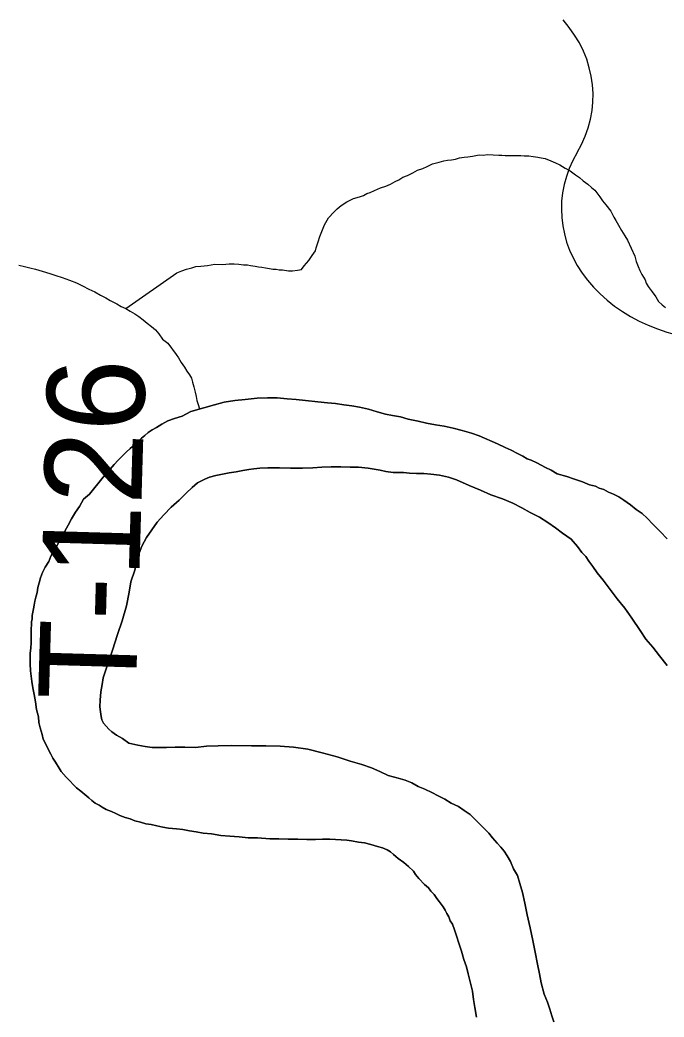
# Model space of a CAD drawing. Extents: x 2.4 to 73.1, y 4.5 to 25.6.
# Drawn here: x 30.7828 to 30.9703, y 21.8149 to 22.105 of the extents above; entities that cross this region are included whole.
import ezdxf

# ---------------------------------------------------------------- set-up
doc = ezdxf.new("R2010")
doc.units = 0
for name, color, linetype in [('GM_X_Major_River', 7, 'Continuous'), ('GM_X_Minor_River', 7, 'Continuous'), ('GM_X_Township_Road_Text', 7, 'Continuous'), ('GM_X_US_Shield', 7, 'Continuous')]:
    doc.layers.add(name, color=color, linetype=linetype)

msp = doc.modelspace()

# ---------------------------------------------------------------- linework, layer by layer
at = {"layer": 'GM_X_Major_River'}
for points in [[(30.92574, 21.97985), (30.92404, 21.98063), (30.92177, 21.98162), (30.91648, 21.98399), (30.91421, 21.98478), (30.91156, 21.98559), (30.90891, 21.9862), (30.90626, 21.98681), (30.90379, 21.98723), (30.90114, 21.98766), (30.89867, 21.98827), (30.89583, 21.98888), (30.89356, 21.98949), (30.89128, 21.98991), (30.8892, 21.99032), (30.88673, 21.99093), (30.88427, 21.99173), (30.88162, 21.99234), (30.87935, 21.99276), (30.87707, 21.99299), (30.8746, 21.99341), (30.87232, 21.99363), (30.86947, 21.99387), (30.86587, 21.99431), (30.86321, 21.99454), (30.86055, 21.99478), (30.8577, 21.99501), (30.85485, 21.99506), (30.8518, 21.99492), (30.84837, 21.99459), (30.84533, 21.99426), (30.84228, 21.99374), (30.83941, 21.99303), (30.83635, 21.99213), (30.83253, 21.99105), (30.83004, 21.98976), (30.82775, 21.98904), (30.82583, 21.98831), (30.82411, 21.98739), (30.82257, 21.98646), (30.82123, 21.98572), (30.82008, 21.98498), (30.81911, 21.98405), (30.81815, 21.98331), (30.81718, 21.98237), (30.81622, 21.98144), (30.81487, 21.98032), (30.81371, 21.9792), (30.81255, 21.97807), (30.81139, 21.97695), (30.81023, 21.97564), (30.80907, 21.97433), (30.80791, 21.97302), (30.80422, 21.96852), (30.80306, 21.96702), (30.80132, 21.96553), (30.80015, 21.96346), (30.79898, 21.96177), (30.79781, 21.95988), (30.79683, 21.958), (30.79585, 21.95631), (30.79507, 21.9548), (30.79429, 21.95348), (30.7935, 21.95197), (30.79253, 21.95047), (30.79175, 21.94896), (30.79115, 21.94745), (30.79017, 21.94576), (30.78939, 21.94425), (30.7888, 21.94274), (30.78839, 21.94123), (30.78799, 21.9399), (30.78778, 21.93839), (30.78737, 21.93706), (30.78717, 21.93593), (30.78696, 21.93479), (30.78675, 21.93365), (30.78655, 21.93271), (30.78634, 21.93176), (30.78633, 21.93081), (30.78612, 21.92986), (30.78611, 21.92891), (30.78609, 21.92796), (30.78607, 21.92682), (30.78605, 21.9253), (30.78603, 21.92379), (30.786, 21.92227), (30.78579, 21.92075), (30.78576, 21.91923), (30.78574, 21.91771), (30.7859, 21.91562), (30.78606, 21.91409), (30.78623, 21.91257), (30.78658, 21.91067), (30.78693, 21.90876), (30.78728, 21.90666), (30.78762, 21.90438), (30.78816, 21.90228), (30.78832, 21.90057), (30.78868, 21.89904), (30.78922, 21.89713)], [(30.78922, 21.89713), (30.78868, 21.89904), (30.78832, 21.90057), (30.78816, 21.90228), (30.78762, 21.90438), (30.78728, 21.90666), (30.78693, 21.90876), (30.78658, 21.91067), (30.78623, 21.91257), (30.78606, 21.91409), (30.7859, 21.91562), (30.78574, 21.91771), (30.78576, 21.91923), (30.78579, 21.92075), (30.786, 21.92227), (30.78603, 21.92379), (30.78605, 21.9253), (30.78607, 21.92682), (30.78609, 21.92796), (30.78611, 21.92891), (30.78612, 21.92986), (30.78633, 21.93081), (30.78634, 21.93176), (30.78655, 21.93271), (30.78675, 21.93365), (30.78696, 21.93479), (30.78717, 21.93593), (30.78737, 21.93706), (30.78778, 21.93839), (30.78799, 21.9399), (30.78839, 21.94123), (30.7888, 21.94274), (30.78939, 21.94425), (30.79017, 21.94576), (30.79115, 21.94745), (30.79175, 21.94896), (30.79253, 21.95047), (30.7935, 21.95197), (30.79429, 21.95348), (30.79507, 21.9548), (30.79585, 21.95631), (30.79683, 21.958), (30.79781, 21.95988), (30.79898, 21.96177), (30.80015, 21.96346), (30.80132, 21.96553), (30.80306, 21.96702), (30.80422, 21.96852), (30.80791, 21.97302), (30.80907, 21.97433), (30.81023, 21.97564), (30.81139, 21.97695), (30.81255, 21.97807), (30.81371, 21.9792), (30.81487, 21.98032), (30.81622, 21.98144), (30.81718, 21.98237), (30.81815, 21.98331), (30.81911, 21.98405), (30.82008, 21.98498), (30.82123, 21.98572), (30.82257, 21.98646), (30.82411, 21.98739), (30.82583, 21.98831), (30.82775, 21.98904), (30.83004, 21.98976), (30.83253, 21.99105), (30.83635, 21.99213), (30.83941, 21.99303), (30.84228, 21.99374), (30.84533, 21.99426), (30.84837, 21.99459), (30.8518, 21.99492), (30.85485, 21.99506), (30.8577, 21.99501), (30.86055, 21.99478), (30.86321, 21.99454), (30.86587, 21.99431), (30.86947, 21.99387), (30.87232, 21.99363), (30.8746, 21.99341), (30.87707, 21.99299), (30.87935, 21.99276), (30.88162, 21.99234), (30.88427, 21.99173), (30.88673, 21.99093), (30.8892, 21.99032), (30.89128, 21.98991), (30.89356, 21.98949), (30.89583, 21.98888), (30.89867, 21.98827), (30.90114, 21.98766), (30.90379, 21.98723), (30.90626, 21.98681), (30.90891, 21.9862), (30.91156, 21.98559), (30.91421, 21.98478), (30.91648, 21.98399), (30.92177, 21.98162), (30.92404, 21.98063), (30.92574, 21.97985)], [(30.97117, 21.95403), (30.96911, 21.95615), (30.96705, 21.95828), (30.96537, 21.96001), (30.96387, 21.96137), (30.96217, 21.96254), (30.96048, 21.96389), (30.9586, 21.96525), (30.95709, 21.96623), (30.95558, 21.96701), (30.95407, 21.96761), (30.95275, 21.96839), (30.95143, 21.96879), (30.9503, 21.96938), (30.94859, 21.96979), (30.94651, 21.97058), (30.94424, 21.97138), (30.94197, 21.97217), (30.93913, 21.97298), (30.93744, 21.97396), (30.93574, 21.97474), (30.93329, 21.97611), (30.93159, 21.9769), (30.93045, 21.9773), (30.92913, 21.97808), (30.92762, 21.97887), (30.92574, 21.97985)], [(30.92574, 21.97985), (30.92762, 21.97887), (30.92913, 21.97808), (30.93045, 21.9773), (30.93159, 21.9769), (30.93329, 21.97611), (30.93574, 21.97474), (30.93744, 21.97396), (30.93913, 21.97298), (30.94197, 21.97217), (30.94424, 21.97138), (30.94651, 21.97058), (30.94859, 21.96979), (30.9503, 21.96938), (30.95143, 21.96879), (30.95275, 21.96839), (30.95407, 21.96761), (30.95558, 21.96701), (30.95709, 21.96623), (30.9586, 21.96525), (30.96048, 21.96389), (30.96217, 21.96254), (30.96387, 21.96137), (30.96537, 21.96001), (30.96705, 21.95828), (30.96911, 21.95615), (30.97117, 21.95403)], [(30.93206, 21.83724), (30.93135, 21.84086), (30.93046, 21.84467), (30.92976, 21.8481), (30.92904, 21.85116), (30.92832, 21.85383), (30.9276, 21.85612), (30.92649, 21.85804), (30.92557, 21.86014), (30.92465, 21.86187), (30.92372, 21.86321), (30.92278, 21.86437), (30.92166, 21.86553), (30.92035, 21.86707), (30.91923, 21.86842), (30.91792, 21.86977), (30.9138, 21.87382), (30.91211, 21.87499), (30.91042, 21.87616), (30.90834, 21.87714), (30.90646, 21.87831), (30.90457, 21.87929), (30.90269, 21.88028), (30.90061, 21.88126), (30.89872, 21.88205), (30.89683, 21.88303), (30.89494, 21.88382), (30.89286, 21.88443), (30.89002, 21.88523), (30.88757, 21.88641), (30.88511, 21.8874), (30.88227, 21.8884), (30.87887, 21.8894), (30.87508, 21.8906), (30.87073, 21.89181), (30.86656, 21.89283), (30.86238, 21.89347), (30.85858, 21.89372), (30.8544, 21.89379), (30.85022, 21.89386), (30.84451, 21.89395), (30.84052, 21.89383), (30.83709, 21.89369), (30.83385, 21.89336), (30.83081, 21.89341), (30.82796, 21.89346), (30.82549, 21.89331), (30.82339, 21.89335), (30.8213, 21.89338), (30.81921, 21.8936), (30.81713, 21.89402), (30.81448, 21.89463), (30.8126, 21.89599), (30.8109, 21.89697), (30.80958, 21.89794), (30.80864, 21.89872), (30.80715, 21.90045), (30.80659, 21.90141), (30.80642, 21.90236), (30.80625, 21.9037), (30.80608, 21.90522), (30.80611, 21.90712), (30.80634, 21.90958), (30.80676, 21.91167), (30.80698, 21.91356), (30.80976, 21.92169), (30.81117, 21.92623), (30.81256, 21.93019), (30.81377, 21.93454), (30.81459, 21.93852), (30.81502, 21.94155), (30.81622, 21.94495), (30.81723, 21.94912), (30.81823, 21.95195), (30.8196, 21.9544), (30.82115, 21.95665), (30.82271, 21.95891), (30.82464, 21.96097), (30.82677, 21.96321), (30.82909, 21.96527), (30.83121, 21.96732), (30.83295, 21.969), (30.83449, 21.97031), (30.8366, 21.97141), (30.83794, 21.97196), (30.83985, 21.9725), (30.84176, 21.97285), (30.84367, 21.9732), (30.84576, 21.97354), (30.84767, 21.97389), (30.84939, 21.97425), (30.85091, 21.97441), (30.85263, 21.97457), (30.85491, 21.97473), (30.85833, 21.97467), (30.86156, 21.97462), (30.86499, 21.97456), (30.86803, 21.9747), (30.8707, 21.97485), (30.87336, 21.975), (30.87621, 21.97495)], [(30.87621, 21.97495), (30.87336, 21.975), (30.8707, 21.97485), (30.86803, 21.9747), (30.86499, 21.97456), (30.86156, 21.97462), (30.85833, 21.97467), (30.85491, 21.97473), (30.85263, 21.97457), (30.85091, 21.97441), (30.84939, 21.97425), (30.84767, 21.97389), (30.84576, 21.97354), (30.84367, 21.9732), (30.84176, 21.97285), (30.83985, 21.9725), (30.83794, 21.97196), (30.8366, 21.97141), (30.83449, 21.97031), (30.83295, 21.969), (30.83121, 21.96732), (30.82909, 21.96527), (30.82677, 21.96321), (30.82464, 21.96097), (30.82271, 21.95891), (30.82115, 21.95665), (30.8196, 21.9544), (30.81823, 21.95195), (30.81723, 21.94912), (30.81622, 21.94495), (30.81502, 21.94155), (30.81459, 21.93852), (30.81377, 21.93454), (30.81256, 21.93019), (30.81117, 21.92623), (30.80976, 21.92169), (30.80698, 21.91356), (30.80676, 21.91167), (30.80634, 21.90958), (30.80611, 21.90712), (30.80608, 21.90522), (30.80625, 21.9037), (30.80642, 21.90236), (30.80659, 21.90141), (30.80715, 21.90045), (30.80864, 21.89872), (30.80958, 21.89794), (30.8109, 21.89697), (30.8126, 21.89599), (30.81448, 21.89463), (30.81713, 21.89402), (30.81921, 21.8936), (30.8213, 21.89338), (30.82339, 21.89335), (30.82549, 21.89331), (30.82796, 21.89346), (30.83081, 21.89341), (30.83385, 21.89336), (30.83709, 21.89369), (30.84052, 21.89383), (30.84451, 21.89395), (30.85022, 21.89386), (30.8544, 21.89379), (30.85858, 21.89372), (30.86238, 21.89347), (30.86656, 21.89283), (30.87073, 21.89181), (30.87508, 21.8906), (30.87887, 21.8894), (30.88227, 21.8884), (30.88511, 21.8874), (30.88757, 21.88641), (30.89002, 21.88523), (30.89286, 21.88443), (30.89494, 21.88382), (30.89683, 21.88303), (30.89872, 21.88205), (30.90061, 21.88126), (30.90269, 21.88028), (30.90457, 21.87929), (30.90646, 21.87831), (30.90834, 21.87714), (30.91042, 21.87616), (30.91211, 21.87499), (30.9138, 21.87382), (30.91792, 21.86977), (30.91923, 21.86842), (30.92035, 21.86707), (30.92166, 21.86553), (30.92278, 21.86437), (30.92372, 21.86321), (30.92465, 21.86187), (30.92557, 21.86014), (30.92649, 21.85804), (30.9276, 21.85612), (30.92832, 21.85383), (30.92904, 21.85116), (30.92976, 21.8481), (30.93046, 21.84467), (30.93135, 21.84086), (30.93206, 21.83724)], [(30.87621, 21.97495), (30.87888, 21.97491), (30.88135, 21.97487), (30.8842, 21.97463), (30.88761, 21.974), (30.88932, 21.9736), (30.8914, 21.97337), (30.89235, 21.97336), (30.8933, 21.97334), (30.89445, 21.97332), (30.89615, 21.97311), (30.89825, 21.97307), (30.90034, 21.97304), (30.90242, 21.97281), (30.90489, 21.97258), (30.90755, 21.97197), (30.90982, 21.97117), (30.9136, 21.96959), (30.91681, 21.96821), (30.91983, 21.96683), (30.92323, 21.96564), (30.92626, 21.96445), (30.9289, 21.96307), (30.93135, 21.9617), (30.93399, 21.96033), (30.93644, 21.95877), (30.9387, 21.95722), (30.94076, 21.95566), (30.94321, 21.95391), (30.94508, 21.95179), (30.94638, 21.95006), (30.9475, 21.9489), (30.94843, 21.94756), (30.94955, 21.94602), (30.95085, 21.9441), (30.95253, 21.94198), (30.95458, 21.93929), (30.95663, 21.93659), (30.95887, 21.9339), (30.96092, 21.93101), (30.96333, 21.92736), (30.965, 21.92487), (30.96706, 21.92255), (30.96892, 21.92005), (30.97116, 21.91717)], [(30.97116, 21.91717), (30.96892, 21.92005), (30.96706, 21.92255), (30.965, 21.92487), (30.96333, 21.92736), (30.96092, 21.93101), (30.95887, 21.9339), (30.95663, 21.93659), (30.95458, 21.93929), (30.95253, 21.94198), (30.95085, 21.9441), (30.94955, 21.94602), (30.94843, 21.94756), (30.9475, 21.9489), (30.94638, 21.95006), (30.94508, 21.95179), (30.94321, 21.95391), (30.94076, 21.95566), (30.9387, 21.95722), (30.93644, 21.95877), (30.93399, 21.96033), (30.93135, 21.9617), (30.9289, 21.96307), (30.92626, 21.96445), (30.92323, 21.96564), (30.91983, 21.96683), (30.91681, 21.96821), (30.9136, 21.96959), (30.90982, 21.97117), (30.90755, 21.97197), (30.90489, 21.97258), (30.90242, 21.97281), (30.90034, 21.97304), (30.89825, 21.97307), (30.89615, 21.97311), (30.89445, 21.97332), (30.8933, 21.97334), (30.89235, 21.97336), (30.8914, 21.97337), (30.88932, 21.9736), (30.88761, 21.974), (30.8842, 21.97463), (30.88135, 21.97487), (30.87888, 21.97491), (30.87621, 21.97495)], [(30.78922, 21.89713), (30.78958, 21.8958), (30.79179, 21.89139), (30.79235, 21.89024), (30.79309, 21.88909), (30.7942, 21.88736), (30.79476, 21.8864), (30.79625, 21.88467), (30.79737, 21.88351), (30.79831, 21.88254), (30.79925, 21.88158), (30.80056, 21.88061), (30.80169, 21.87964), (30.80281, 21.87867), (30.80375, 21.87789), (30.80469, 21.87712), (30.80582, 21.87653), (30.80677, 21.87595), (30.8079, 21.87536), (30.80941, 21.87476), (30.81073, 21.87417), (30.81186, 21.87358), (30.81338, 21.87299), (30.81489, 21.87258), (30.81621, 21.87199), (30.81792, 21.87158), (30.81943, 21.87118), (30.82095, 21.87096), (30.82266, 21.87056), (30.82436, 21.87015), (30.82607, 21.86993), (30.82835, 21.8697), (30.83025, 21.86948), (30.83214, 21.86907), (30.83404, 21.86885), (30.83613, 21.86844), (30.83859, 21.86821), (30.84125, 21.86778), (30.84391, 21.86755), (30.84657, 21.86732), (30.84923, 21.86708), (30.85189, 21.86704), (30.8555, 21.86679), (30.85816, 21.86675), (30.86082, 21.86671), (30.86367, 21.86666), (30.86634, 21.86661), (30.86881, 21.86657), (30.8709, 21.86673), (30.87299, 21.8667), (30.87793, 21.86643), (30.87926, 21.86622), (30.88135, 21.8658), (30.88306, 21.86558), (30.88495, 21.86517), (30.88684, 21.86457), (30.88836, 21.86417), (30.88968, 21.86358), (30.89062, 21.86299), (30.89156, 21.86222), (30.89287, 21.86105), (30.89457, 21.85989), (30.89588, 21.85872), (30.89738, 21.85737), (30.89794, 21.85641), (30.89887, 21.85526), (30.90055, 21.85352), (30.90168, 21.85255), (30.90242, 21.85159), (30.90336, 21.85062), (30.9041, 21.84947), (30.90485, 21.84851), (30.90597, 21.84697), (30.90652, 21.84601), (30.90708, 21.84505), (30.90763, 21.84409), (30.908, 21.84295), (30.90874, 21.84199), (30.90928, 21.84027), (30.90983, 21.83855), (30.91055, 21.83645), (30.91128, 21.83415), (30.912, 21.83167), (30.91273, 21.82957), (30.91327, 21.82747), (30.9138, 21.82518), (30.91452, 21.82251), (30.91486, 21.82003), (30.91521, 21.81775), (30.91573, 21.81489)], [(30.91573, 21.81489), (30.91521, 21.81775), (30.91486, 21.82003), (30.91452, 21.82251), (30.9138, 21.82518), (30.91327, 21.82747), (30.91273, 21.82957), (30.912, 21.83167), (30.91128, 21.83415), (30.91055, 21.83645), (30.90983, 21.83855), (30.90928, 21.84027), (30.90874, 21.84199), (30.908, 21.84295), (30.90763, 21.84409), (30.90708, 21.84505), (30.90652, 21.84601), (30.90597, 21.84697), (30.90485, 21.84851), (30.9041, 21.84947), (30.90336, 21.85062), (30.90242, 21.85159), (30.90168, 21.85255), (30.90055, 21.85352), (30.89887, 21.85526), (30.89794, 21.85641), (30.89738, 21.85737), (30.89588, 21.85872), (30.89457, 21.85989), (30.89287, 21.86105), (30.89156, 21.86222), (30.89062, 21.86299), (30.88968, 21.86358), (30.88836, 21.86417), (30.88684, 21.86457), (30.88495, 21.86517), (30.88306, 21.86558), (30.88135, 21.8658), (30.87926, 21.86622), (30.87793, 21.86643), (30.87299, 21.8667), (30.8709, 21.86673), (30.86881, 21.86657), (30.86634, 21.86661), (30.86367, 21.86666), (30.86082, 21.86671), (30.85816, 21.86675), (30.8555, 21.86679), (30.85189, 21.86704), (30.84923, 21.86708), (30.84657, 21.86732), (30.84391, 21.86755), (30.84125, 21.86778), (30.83859, 21.86821), (30.83613, 21.86844), (30.83404, 21.86885), (30.83214, 21.86907), (30.83025, 21.86948), (30.82835, 21.8697), (30.82607, 21.86993), (30.82436, 21.87015), (30.82266, 21.87056), (30.82095, 21.87096), (30.81943, 21.87118), (30.81792, 21.87158), (30.81621, 21.87199), (30.81489, 21.87258), (30.81338, 21.87299), (30.81186, 21.87358), (30.81073, 21.87417), (30.80941, 21.87476), (30.8079, 21.87536), (30.80677, 21.87595), (30.80582, 21.87653), (30.80469, 21.87712), (30.80375, 21.87789), (30.80281, 21.87867), (30.80169, 21.87964), (30.80056, 21.88061), (30.79925, 21.88158), (30.79831, 21.88254), (30.79737, 21.88351), (30.79625, 21.88467), (30.79476, 21.8864), (30.7942, 21.88736), (30.79309, 21.88909), (30.79235, 21.89024), (30.79179, 21.89139), (30.78958, 21.8958), (30.78922, 21.89713)], [(30.93815, 21.81358), (30.93761, 21.8153), (30.93707, 21.8172), (30.93634, 21.81931), (30.93543, 21.8216), (30.93453, 21.82485), (30.934, 21.82751), (30.93347, 21.83037), (30.93276, 21.83381), (30.93206, 21.83724)], [(30.93206, 21.83724), (30.93276, 21.83381), (30.93347, 21.83037), (30.934, 21.82751), (30.93453, 21.82485), (30.93543, 21.8216), (30.93634, 21.81931), (30.93707, 21.8172), (30.93761, 21.8153), (30.93815, 21.81358)]]:
    msp.add_lwpolyline(points, dxfattribs=at)
at = {"layer": 'GM_X_Minor_River'}
for points in [[(30.81361, 22.021), (30.82841, 22.0314), (30.82994, 22.03194), (30.83128, 22.03249), (30.83281, 22.03285), (30.83396, 22.03321), (30.83548, 22.03337), (30.83738, 22.03353), (30.83948, 22.03388), (30.84176, 22.03384), (30.84367, 22.034), (30.84519, 22.03398), (30.84652, 22.03396), (30.84785, 22.03374), (30.84899, 22.03373), (30.84994, 22.03352), (30.85126, 22.03331), (30.85221, 22.0331), (30.85316, 22.03309), (30.8543, 22.03288), (30.85544, 22.03267), (30.85639, 22.03247), (30.85734, 22.03245), (30.85828, 22.03224), (30.85924, 22.03223), (30.86094, 22.03201), (30.86208, 22.03199), (30.86361, 22.03216), (30.86475, 22.03233), (30.86553, 22.03346), (30.86689, 22.03495), (30.86786, 22.03646), (30.86883, 22.03777), (30.86904, 22.03872), (30.86963, 22.04042), (30.87004, 22.04193), (30.87063, 22.04344), (30.87103, 22.04439), (30.87142, 22.04533), (30.8726, 22.0474), (30.87414, 22.04909), (30.87511, 22.05002), (30.87626, 22.05095), (30.87799, 22.05206), (30.87991, 22.05298), (30.88163, 22.05353), (30.88278, 22.05389), (30.88374, 22.05444), (30.88469, 22.05481), (30.88603, 22.05535), (30.88776, 22.05609), (30.88929, 22.05663), (30.89063, 22.05718), (30.89197, 22.05792), (30.89312, 22.05847), (30.89427, 22.05921), (30.89561, 22.05976), (30.89715, 22.06049), (30.89849, 22.06123), (30.90002, 22.06178), (30.90136, 22.06233), (30.90289, 22.06306), (30.9048, 22.0636), (30.90614, 22.06396), (30.90728, 22.06413), (30.90842, 22.0643), (30.90957, 22.06447), (30.91072, 22.06483), (30.91205, 22.065), (30.91319, 22.06517), (30.91453, 22.06534), (30.91548, 22.06552), (30.91644, 22.06569), (30.91758, 22.06567), (30.91891, 22.06584), (30.92214, 22.0656), (30.92309, 22.06558), (30.92404, 22.06557), (30.92518, 22.06555), (30.92613, 22.06553), (30.92708, 22.06552), (30.9286, 22.06549), (30.92955, 22.06548), (30.93088, 22.06546), (30.93221, 22.06525), (30.93354, 22.06503), (30.93449, 22.06483), (30.93563, 22.06462), (30.93733, 22.06402), (30.93865, 22.06343), (30.93997, 22.06284), (30.94148, 22.06187), (30.94299, 22.06108), (30.94449, 22.05992), (30.94562, 22.05914), (30.94675, 22.05817), (30.94806, 22.0572)], [(30.94806, 22.0572), (30.94919, 22.05623), (30.95013, 22.05545), (30.95162, 22.05353), (30.95236, 22.05238), (30.95329, 22.05122), (30.95478, 22.0493), (30.95571, 22.04757), (30.95626, 22.04662), (30.957, 22.04527), (30.95793, 22.04374), (30.95886, 22.0422), (30.9596, 22.04086), (30.96181, 22.03627), (30.96216, 22.03474), (30.96271, 22.03321), (30.96326, 22.03206), (30.96382, 22.03091), (30.96474, 22.02938), (30.96511, 22.02842), (30.96566, 22.02746), (30.96678, 22.02592), (30.9679, 22.02439), (30.96864, 22.02304), (30.96976, 22.02208), (30.9707, 22.0213)], [(30.78242, 22.03367), (30.78413, 22.03326), (30.78564, 22.03286), (30.78735, 22.03245), (30.78924, 22.03185), (30.79151, 22.03124), (30.79322, 22.03064), (30.79511, 22.03004), (30.79719, 22.02925), (30.79927, 22.02845), (30.80097, 22.02767), (30.80285, 22.02669), (30.80455, 22.0259), (30.80625, 22.02492), (30.80776, 22.02414), (30.80908, 22.02335), (30.81096, 22.02237), (30.81228, 22.02159), (30.81361, 22.021), (30.81492, 22.02022), (30.81624, 22.01944), (30.81737, 22.01866), (30.81869, 22.01769), (30.81981, 22.01672), (30.82113, 22.01575), (30.82226, 22.01478), (30.82319, 22.01362), (30.82431, 22.01209)], [(30.82431, 22.01209), (30.82581, 22.01092), (30.82823, 22.00765), (30.82898, 22.00669), (30.82972, 22.00535), (30.83065, 22.004), (30.83139, 22.00285), (30.83213, 22.0017), (30.83269, 22.00074), (30.83305, 21.99959), (30.83341, 21.99826), (30.83376, 21.99673), (30.83412, 21.9954), (30.8343, 21.99425), (30.83466, 21.99311), (30.83504, 21.99181)]]:
    msp.add_lwpolyline(points, dxfattribs=at)
at = {"layer": 'GM_X_US_Shield'}
for centre, start_param, end_param in [((30.90155, 22.0829), 5.838949, 6.894067), ((30.98845, 22.05002), 2.702327, 4.723529)]:
    msp.add_ellipse(centre, major_axis=(0.04807, 0), ratio=0.8, start_param=start_param, end_param=end_param, dxfattribs=at)

# ---------------------------------------------------------------- texts
at = {"layer": 'GM_X_Township_Road_Text'}
msp.add_text('T-126', height=0.028409, rotation=88.3318, dxfattribs=at).set_placement((30.81646, 21.90679))

doc.saveas('drawing.dxf')
